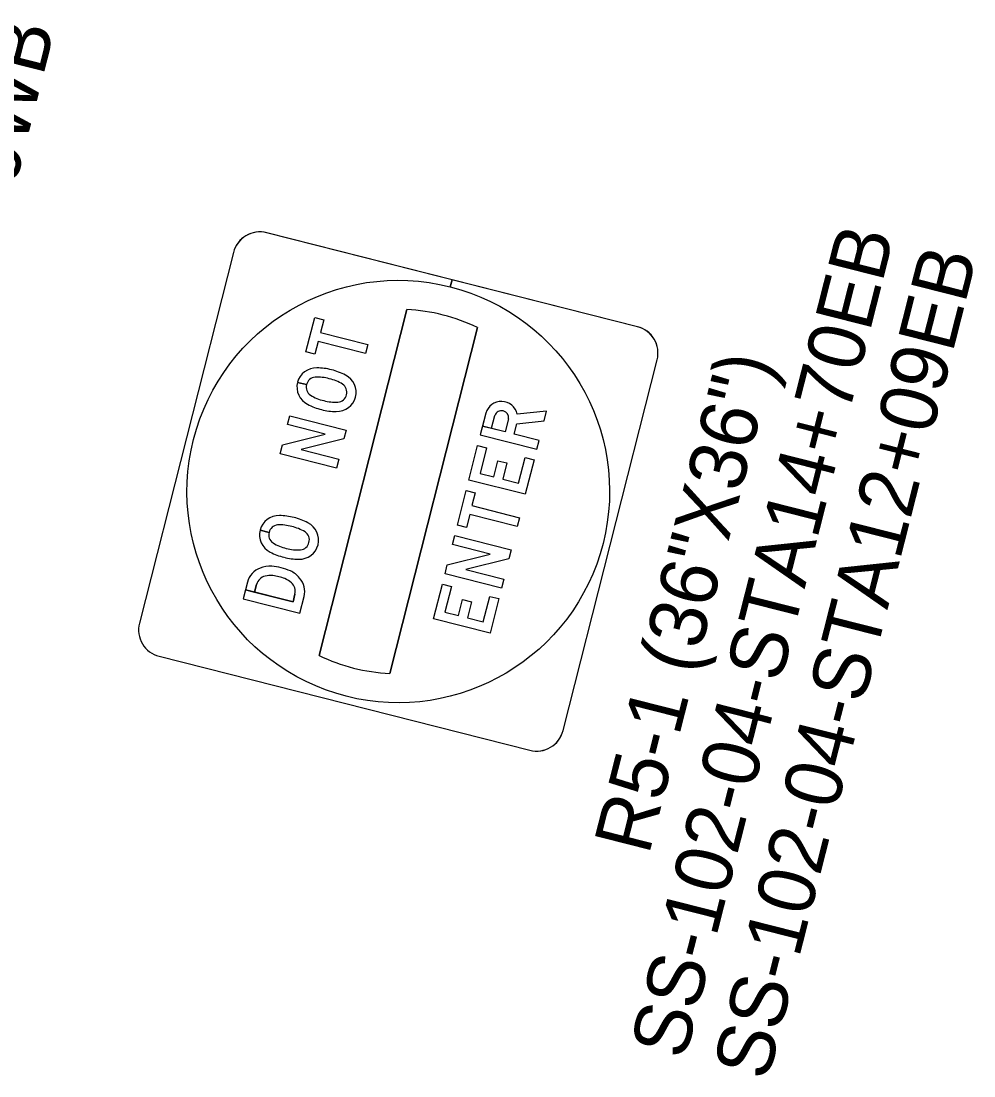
# Model space of a CAD drawing. Extents: x 670257 to 671518, y 737783 to 738188.
# Drawn here: x 670281.168 to 670285.35, y 738163.049 to 738167.682 of the extents above; entities that cross this region are included whole.
import ezdxf

# ---------------------------------------------------------------- set-up
doc = ezdxf.new("R2010")
doc.units = 0
doc.layers.add('Default', color=7, linetype='Continuous')
doc.layers.add('R_SIGN_ANNOT', color=7, linetype='Continuous')

msp = doc.modelspace()

# ---------------------------------------------------------------- linework, layer by layer
at = {"layer": 'Default'}
for p, q in [((670283.8729, 738166.3396), (670282.2455, 738166.7524)), ((670283.8729, 738166.3396), (670282.2455, 738166.7524)), ((670283.8729, 738166.3396), (670282.2456, 738166.7523)), ((670283.0593, 738166.5459), (670282.2456, 738166.7523)), ((670283.0593, 738166.5459), (670282.2456, 738166.7523)), ((670282.0998, 738166.6656), (670281.6869, 738165.0377)), ((670282.0998, 738166.6656), (670281.6869, 738165.0377)), ((670282.0999, 738166.6655), (670281.687, 738165.0376)), ((670282.0999, 738166.6655), (670281.687, 738165.0376)), ((670282.0999, 738166.6655), (670281.687, 738165.0376)), ((670283.0593, 738166.5459), (670283.0514, 738166.5149)), ((670283.8729, 738166.3396), (670283.0593, 738166.546)), ((670283.8729, 738166.3396), (670283.0593, 738166.546)), ((670282.861, 738166.4145), (670282.4757, 738164.8955)), ((670282.7857, 738164.8169), (670283.1709, 738166.3359)), ((670283.5468, 738164.566), (670283.9596, 738166.1939)), ((670283.5468, 738164.566), (670283.9596, 738166.1939)), ((670283.5468, 738164.566), (670283.9596, 738166.1939)), ((670283.5468, 738164.566), (670283.9596, 738166.1939)), ((670283.5468, 738164.566), (670283.9596, 738166.1938)), ((670282.4208, 738166.0851), (670282.3809, 738166.0952)), ((670282.3809, 738166.0952), (670282.4208, 738166.0851)), ((670282.4208, 738166.0851), (670282.3809, 738166.0952)), ((670282.3809, 738166.0952), (670282.4208, 738166.0851)), ((670282.4208, 738166.0851), (670282.4208, 738166.0851)), ((670282.4208, 738166.0851), (670282.4208, 738166.0851)), ((670283.3073, 738165.9343), (670283.293, 738165.8779)), ((670282.2562, 738165.4363), (670282.2163, 738165.4464)), ((670282.2163, 738165.4464), (670282.2562, 738165.4363)), ((670282.2562, 738165.4363), (670282.2163, 738165.4464)), ((670282.2163, 738165.4464), (670282.2562, 738165.4363)), ((670282.2562, 738165.4363), (670282.2562, 738165.4363)), ((670282.2562, 738165.4363), (670282.2562, 738165.4363)), ((670282.2012, 738165.2076), (670282.1927, 738165.1741)), ((670282.3698, 738165.1648), (670282.3613, 738165.1314)), ((670282.3698, 738165.1648), (670282.3613, 738165.1314)), ((670282.391, 738165.0819), (670282.4095, 738165.1548)), ((670281.7737, 738164.8919), (670283.401, 738164.4792)), ((670281.7737, 738164.8919), (670283.401, 738164.4792)), ((670281.7737, 738164.8919), (670283.401, 738164.4792)), ((670281.7737, 738164.8919), (670283.401, 738164.4792)), ((670281.7737, 738164.8919), (670283.401, 738164.4792))]:
    msp.add_line(p, q, dxfattribs=at)
for points in [[(670283.0593, 738166.546), (670283.0514, 738166.5149)], [(670283.0514, 738166.5149), (670283.0593, 738166.5459)], [(670283.0514, 738166.5149), (670283.0592, 738166.5459)], [(670282.4757, 738164.8955), (670282.4757, 738164.8956), (670282.861, 738166.4145), (670282.861, 738166.4146)], [(670283.1709, 738166.336), (670283.1709, 738166.3359), (670282.7856, 738164.817), (670282.7856, 738164.8169)], [(670283.2074, 738165.9596), (670283.1832, 738165.8642), (670283.4312, 738165.8013), (670283.4411, 738165.8404), (670283.3327, 738165.8679), (670283.3442, 738165.9134)], [(670283.3073, 738165.9343), (670283.293, 738165.8779), (670283.1931, 738165.9033), (670283.1832, 738165.8642), (670283.4312, 738165.8013)], [(670283.3073, 738165.9343), (670283.293, 738165.8779), (670283.1931, 738165.9033), (670283.1832, 738165.8642), (670283.4312, 738165.8013)], [(670283.2074, 738165.9596), (670283.1931, 738165.9033), (670283.2328, 738165.8933), (670283.2471, 738165.9496)], [(670283.2074, 738165.9596), (670283.1931, 738165.9033), (670283.2328, 738165.8933), (670283.2471, 738165.9496)], [(670283.293, 738165.8779), (670283.2328, 738165.8932), (670283.2471, 738165.9496)], [(670283.4312, 738165.8013), (670283.4411, 738165.8404), (670283.3327, 738165.8679), (670283.3442, 738165.9134), (670283.463, 738165.9268), (670283.4736, 738165.9687), (670283.3456, 738165.9559)], [(670283.4312, 738165.8013), (670283.4411, 738165.8404), (670283.3327, 738165.8679), (670283.3442, 738165.9134), (670283.463, 738165.9268), (670283.4736, 738165.9687), (670283.3456, 738165.9559)], [(670283.3442, 738165.9134), (670283.463, 738165.9268), (670283.4736, 738165.9687), (670283.3456, 738165.9559)], [(670282.1615, 738165.2177), (670282.143, 738165.1447), (670282.391, 738165.0819)], [(670282.1615, 738165.2177), (670282.153, 738165.1842), (670282.1927, 738165.1741), (670282.2012, 738165.2076)], [(670282.1615, 738165.2177), (670282.153, 738165.1842), (670282.1927, 738165.1741), (670282.2012, 738165.2076)], [(670282.3613, 738165.1314), (670282.153, 738165.1842), (670282.143, 738165.1447), (670282.391, 738165.0819), (670282.4095, 738165.1548)], [(670282.3613, 738165.1314), (670282.153, 738165.1842), (670282.143, 738165.1447), (670282.391, 738165.0819), (670282.4095, 738165.1548)], [(670282.1927, 738165.1741), (670282.3613, 738165.1314), (670282.3698, 738165.1648)]]:
    msp.add_lwpolyline(points, dxfattribs=at)
for points in [[(670282.4563, 738166.38), (670282.496, 738166.3699), (670282.4817, 738166.3137), (670282.6901, 738166.2609), (670282.6801, 738166.2218), (670282.4718, 738166.2746), (670282.4576, 738166.2184), (670282.4179, 738166.2285)], [(670282.4563, 738166.38), (670282.496, 738166.3699), (670282.4817, 738166.3137), (670282.6901, 738166.2609), (670282.6801, 738166.2218), (670282.4718, 738166.2746), (670282.4576, 738166.2184), (670282.4179, 738166.2285)], [(670282.4563, 738166.38), (670282.496, 738166.3699), (670282.4817, 738166.3137), (670282.6901, 738166.2609), (670282.6801, 738166.2218), (670282.4718, 738166.2746), (670282.4576, 738166.2184), (670282.4179, 738166.2285)], [(670282.5525, 738165.7184), (670282.3045, 738165.7813), (670282.3145, 738165.8209), (670282.5021, 738165.8678), (670282.337, 738165.9096), (670282.3469, 738165.9487), (670282.5949, 738165.8858), (670282.585, 738165.8467), (670282.3964, 738165.7996), (670282.5624, 738165.7575)], [(670282.5525, 738165.7184), (670282.3045, 738165.7813), (670282.3145, 738165.8209), (670282.5021, 738165.8678), (670282.337, 738165.9096), (670282.3469, 738165.9487), (670282.5949, 738165.8858), (670282.585, 738165.8467), (670282.3964, 738165.7996), (670282.5624, 738165.7575)], [(670282.5525, 738165.7184), (670282.3045, 738165.7813), (670282.3145, 738165.8209), (670282.5021, 738165.8678), (670282.337, 738165.9096), (670282.3469, 738165.9487), (670282.5949, 738165.8858), (670282.585, 738165.8467), (670282.3964, 738165.7996), (670282.5624, 738165.7575)], [(670283.2111, 738165.8077), (670283.1826, 738165.6953), (670283.2421, 738165.6802), (670283.2601, 738165.7512), (670283.2998, 738165.7412), (670283.2818, 738165.6701), (670283.3512, 738165.6525), (670283.3797, 738165.7649), (670283.4194, 738165.7549), (670283.381, 738165.6034), (670283.133, 738165.6662), (670283.1714, 738165.8177)], [(670283.2111, 738165.8077), (670283.1826, 738165.6953), (670283.2421, 738165.6802), (670283.2601, 738165.7512), (670283.2998, 738165.7412), (670283.2818, 738165.6701), (670283.3512, 738165.6525), (670283.3797, 738165.7649), (670283.4194, 738165.7549), (670283.381, 738165.6034), (670283.133, 738165.6662), (670283.1714, 738165.8177)], [(670283.2111, 738165.8077), (670283.1826, 738165.6953), (670283.2421, 738165.6802), (670283.2601, 738165.7512), (670283.2998, 738165.7412), (670283.2818, 738165.6701), (670283.3512, 738165.6525), (670283.3797, 738165.7649), (670283.4194, 738165.7549), (670283.381, 738165.6034), (670283.133, 738165.6662), (670283.1714, 738165.8177)], [(670283.1212, 738165.6199), (670283.1609, 738165.6098), (670283.1467, 738165.5536), (670283.355, 738165.5008), (670283.345, 738165.4616), (670283.1367, 738165.5145), (670283.1225, 738165.4583), (670283.0828, 738165.4684)], [(670283.1212, 738165.6199), (670283.1609, 738165.6098), (670283.1467, 738165.5536), (670283.355, 738165.5008), (670283.345, 738165.4616), (670283.1367, 738165.5145), (670283.1225, 738165.4583), (670283.0828, 738165.4684)], [(670283.1212, 738165.6199), (670283.1609, 738165.6098), (670283.1467, 738165.5536), (670283.355, 738165.5008), (670283.345, 738165.4616), (670283.1367, 738165.5145), (670283.1225, 738165.4583), (670283.0828, 738165.4684)], [(670283.2766, 738165.1916), (670283.0286, 738165.2545), (670283.0386, 738165.2941), (670283.2262, 738165.3409), (670283.0611, 738165.3828), (670283.071, 738165.4219), (670283.319, 738165.359), (670283.3091, 738165.3199), (670283.1205, 738165.2728), (670283.2865, 738165.2307)], [(670283.2766, 738165.1916), (670283.0286, 738165.2545), (670283.0386, 738165.2941), (670283.2262, 738165.3409), (670283.0611, 738165.3828), (670283.071, 738165.4219), (670283.319, 738165.359), (670283.3091, 738165.3199), (670283.1205, 738165.2728), (670283.2865, 738165.2307)], [(670283.2766, 738165.1916), (670283.0286, 738165.2545), (670283.0386, 738165.2941), (670283.2262, 738165.3409), (670283.0611, 738165.3828), (670283.071, 738165.4219), (670283.319, 738165.359), (670283.3091, 738165.3199), (670283.1205, 738165.2728), (670283.2865, 738165.2307)], [(670283.0565, 738165.1981), (670283.028, 738165.0856), (670283.0875, 738165.0705), (670283.1055, 738165.1416), (670283.1452, 738165.1316), (670283.1272, 738165.0605), (670283.1966, 738165.0429), (670283.2251, 738165.1553), (670283.2648, 738165.1452), (670283.2264, 738164.9937), (670282.9784, 738165.0566), (670283.0168, 738165.2081)], [(670283.0565, 738165.1981), (670283.028, 738165.0856), (670283.0875, 738165.0705), (670283.1055, 738165.1416), (670283.1452, 738165.1316), (670283.1272, 738165.0605), (670283.1966, 738165.0429), (670283.2251, 738165.1553), (670283.2648, 738165.1452), (670283.2264, 738164.9937), (670282.9784, 738165.0566), (670283.0168, 738165.2081)], [(670283.0565, 738165.1981), (670283.028, 738165.0856), (670283.0875, 738165.0705), (670283.1055, 738165.1416), (670283.1452, 738165.1316), (670283.1272, 738165.0605), (670283.1966, 738165.0429), (670283.2251, 738165.1553), (670283.2648, 738165.1452), (670283.2264, 738164.9937), (670282.9784, 738165.0566), (670283.0168, 738165.2081)]]:
    msp.add_lwpolyline(points, close=True, dxfattribs=at)
for centre, major_axis, ratio, start_param, end_param in [((670282.216, 738166.6361), (0.0295, 0.1163), 0.999667, 0, 1.570796), ((670282.216, 738166.6361), (0.0295, 0.1163), 0.999667, 0, 1.570796), ((670282.2161, 738166.636), (0.0295, 0.1163), 0.999667, 6.283185, 7.853982), ((670282.2161, 738166.636), (0.0295, 0.1163), 0.999667, 6.283185, 7.853982), ((670282.2161, 738166.636), (0.0295, 0.1163), 0.999667, 6.283185, 7.853982), ((670282.8233, 738165.6157), (0.2281, 0.8992), 0.999667, 0, 6.283158), ((670282.8233, 738165.6157), (0.2281, 0.8992), 0.999667, 0, 6.283158), ((670282.8233, 738165.6157), (0.2281, 0.8992), 0.999667, 0, 6.283158), ((670282.8233, 738165.6157), (0.1966, 0.7752), 0.999667, 0, 0.201359), ((670282.8233, 738165.6157), (0.1966, 0.7752), 0.999667, 0, 0.201359), ((670282.8233, 738165.6157), (0.1966, 0.7752), 0.999667, 6.081826, 6.283153), ((670282.8233, 738165.6157), (0.1966, 0.7752), 0.999667, 6.081826, 6.283153), ((670283.8434, 738166.2233), (0.0295, 0.1163), 0.999667, 4.712389, 6.283185), ((670283.8434, 738166.2233), (0.0295, 0.1163), 0.999667, 4.712389, 6.283185), ((670283.8434, 738166.2233), (0.0295, 0.1163), 0.999667, 4.712388, 6.283186), ((670283.8434, 738166.2233), (0.0295, 0.1163), 0.999667, 4.712388, 6.283186), ((670283.8434, 738166.2233), (0.0295, 0.1163), 0.999667, 4.712388, 6.283186), ((670282.4646, 738166.0734), (-0.0839, 0.0213), 0.985425, 4.940915, 6.276178), ((670282.4646, 738166.0734), (-0.0839, 0.0213), 0.985425, 4.940915, 6.27603), ((670282.4646, 738166.0734), (-0.0839, 0.0213), 0.985425, 4.940915, 6.27603), ((670282.4625, 738166.0759), (-0.0414, 0.0105), 0.985425, 5.062003, 6.314032), ((670282.4625, 738166.0759), (-0.0414, 0.0105), 0.985425, 5.062003, 6.313732), ((670282.4625, 738166.0759), (-0.0414, 0.0105), 0.985425, 5.062003, 6.313732), ((670282.4694, 738165.9281), (-0.1867, 0.0473), 0.985425, 4.688261, 5.016143), ((670282.4694, 738165.9281), (-0.1867, 0.0473), 0.985425, 4.688261, 5.016143), ((670282.4694, 738165.9281), (-0.1867, 0.0473), 0.985425, 4.688261, 5.016143), ((670282.4656, 738165.8998), (-0.2545, 0.0645), 0.985425, 4.707364, 4.955713), ((670282.4656, 738165.8998), (-0.2545, 0.0645), 0.985425, 4.707364, 4.955713), ((670282.4656, 738165.8998), (-0.2545, 0.0645), 0.985425, 4.707364, 4.955713), ((670282.4682, 738165.8992), (-0.2545, 0.0645), 0.985425, 4.469065, 4.717414), ((670282.4682, 738165.8992), (-0.2545, 0.0645), 0.985425, 4.469065, 4.717414), ((670282.4682, 738165.8992), (-0.2545, 0.0645), 0.985425, 4.469065, 4.717414), ((670282.5518, 738166.0513), (-0.0839, 0.0213), 0.985425, 3.1486, 4.483863), ((670282.5518, 738166.0513), (-0.0839, 0.0213), 0.985425, 3.1486, 4.483863), ((670282.5518, 738166.0513), (-0.0839, 0.0213), 0.985425, 3.1486, 4.483863), ((670282.4649, 738166.0745), (-0.0839, 0.0213), 0.985425, 0.007008, 1.34227), ((670282.4649, 738166.0745), (-0.0839, 0.0213), 0.985425, 0.007008, 1.34227), ((670282.4649, 738166.0745), (-0.0839, 0.0213), 0.985425, 0.007008, 1.34227), ((670282.4619, 738166.0733), (-0.0414, 0.0105), 0.985425, 6.252339, 7.504367), ((670282.4619, 738166.0733), (-0.0414, 0.0105), 0.985425, 6.252339, 7.504367), ((670282.4619, 738166.0733), (-0.0414, 0.0105), 0.985425, 6.252339, 7.504367), ((670282.4784, 738165.9258), (-0.1867, 0.0473), 0.985425, 4.408635, 4.736517), ((670282.4784, 738165.9258), (-0.1867, 0.0473), 0.985425, 4.408635, 4.736517), ((670282.4784, 738165.9258), (-0.1867, 0.0473), 0.985425, 4.408635, 4.736517), ((670282.5548, 738166.0525), (-0.0414, 0.0105), 0.985425, 3.110746, 4.362774), ((670282.5548, 738166.0525), (-0.0414, 0.0105), 0.985425, 3.110746, 4.362775), ((670282.5548, 738166.0525), (-0.0414, 0.0105), 0.985425, 3.110746, 4.362775), ((670282.5383, 738166.2), (-0.1867, 0.0473), 0.985425, 1.267043, 1.594924), ((670282.5383, 738166.2), (-0.1867, 0.0473), 0.985425, 1.267042, 1.594924), ((670282.5383, 738166.2), (-0.1867, 0.0473), 0.985425, 1.267042, 1.594924), ((670282.5521, 738166.0524), (-0.0839, 0.0213), 0.985425, 1.799323, 3.134585), ((670282.5521, 738166.0524), (-0.0839, 0.0213), 0.985425, 1.799323, 3.134585), ((670282.5521, 738166.0524), (-0.0839, 0.0213), 0.985425, 1.799323, 3.134585), ((670282.5542, 738166.0499), (-0.0414, 0.0105), 0.985425, 1.920411, 3.172439), ((670282.5542, 738166.0499), (-0.0414, 0.0105), 0.985425, 1.920411, 3.172439), ((670282.5542, 738166.0499), (-0.0414, 0.0105), 0.985425, 1.920411, 3.172439), ((670282.5485, 738166.2266), (-0.2545, 0.0645), 0.985425, 1.327472, 1.575821), ((670282.5485, 738166.2266), (-0.2545, 0.0645), 0.985425, 1.327472, 1.575821), ((670282.5485, 738166.2266), (-0.2545, 0.0645), 0.985425, 1.327472, 1.575821), ((670282.5473, 738166.1977), (-0.1867, 0.0473), 0.985425, 1.546668, 1.87455), ((670282.5473, 738166.1977), (-0.1867, 0.0473), 0.985425, 1.546668, 1.87455), ((670282.5473, 738166.1977), (-0.1867, 0.0473), 0.985425, 1.546668, 1.87455), ((670283.2762, 738165.9409), (-0.0691, 0.0175), 0.985328, 3.608399, 6.264838), ((670283.2762, 738165.9409), (-0.0691, 0.0175), 0.985328, 3.608399, 6.264838), ((670283.2762, 738165.9409), (-0.0691, 0.0175), 0.985328, 3.608399, 6.264838), ((670282.5511, 738166.226), (-0.2545, 0.0645), 0.985425, 1.565772, 1.814121), ((670282.5511, 738166.226), (-0.2545, 0.0645), 0.985425, 1.565772, 1.814121), ((670282.5511, 738166.226), (-0.2545, 0.0645), 0.985425, 1.565772, 1.814121), ((670283.2767, 738165.9399), (-0.0302, 0.0077), 0.985328, 3.211299, 6.213479), ((670283.2767, 738165.9399), (-0.0302, 0.0077), 0.985328, 3.211299, 6.213479), ((670283.2767, 738165.9399), (-0.0302, 0.0077), 0.985328, 3.211299, 6.213479), ((670282.3001, 738165.4246), (-0.0839, 0.0213), 0.985425, 4.940915, 6.276178), ((670282.3001, 738165.4246), (-0.0839, 0.0213), 0.985425, 4.940915, 6.27603), ((670282.3001, 738165.4246), (-0.0839, 0.0213), 0.985425, 4.940915, 6.27603), ((670282.298, 738165.4271), (-0.0414, 0.0105), 0.985425, 5.062003, 6.314032), ((670282.298, 738165.4271), (-0.0414, 0.0105), 0.985425, 5.062003, 6.313732), ((670282.298, 738165.4271), (-0.0414, 0.0105), 0.985425, 5.062003, 6.313732), ((670282.3048, 738165.2793), (-0.1867, 0.0473), 0.985425, 4.688261, 5.016143), ((670282.3048, 738165.2793), (-0.1867, 0.0473), 0.985425, 4.688261, 5.016143), ((670282.3048, 738165.2793), (-0.1867, 0.0473), 0.985425, 4.688261, 5.016143), ((670282.3011, 738165.251), (-0.2545, 0.0645), 0.985425, 4.707364, 4.955713), ((670282.3011, 738165.251), (-0.2545, 0.0645), 0.985425, 4.707364, 4.955713), ((670282.3011, 738165.251), (-0.2545, 0.0645), 0.985425, 4.707364, 4.955713), ((670282.3036, 738165.2504), (-0.2545, 0.0645), 0.985425, 4.469065, 4.717414), ((670282.3036, 738165.2504), (-0.2545, 0.0645), 0.985425, 4.469065, 4.717414), ((670282.3036, 738165.2504), (-0.2545, 0.0645), 0.985425, 4.469065, 4.717414), ((670282.3872, 738165.4025), (-0.0839, 0.0213), 0.985425, 3.1486, 4.483863), ((670282.3872, 738165.4025), (-0.0839, 0.0213), 0.985425, 3.1486, 4.483863), ((670282.3872, 738165.4025), (-0.0839, 0.0213), 0.985425, 3.1486, 4.483863), ((670282.3004, 738165.4257), (-0.0839, 0.0213), 0.985425, 0.007008, 1.34227), ((670282.3004, 738165.4257), (-0.0839, 0.0213), 0.985425, 0.007008, 1.34227), ((670282.3004, 738165.4257), (-0.0839, 0.0213), 0.985425, 0.007008, 1.34227), ((670282.2973, 738165.4245), (-0.0414, 0.0105), 0.985425, 6.252339, 7.504367), ((670282.2973, 738165.4245), (-0.0414, 0.0105), 0.985425, 6.252339, 7.504367), ((670282.2973, 738165.4245), (-0.0414, 0.0105), 0.985425, 6.252339, 7.504367), ((670282.3138, 738165.277), (-0.1867, 0.0473), 0.985425, 4.408635, 4.736517), ((670282.3138, 738165.277), (-0.1867, 0.0473), 0.985425, 4.408635, 4.736517), ((670282.3138, 738165.277), (-0.1867, 0.0473), 0.985425, 4.408635, 4.736517), ((670282.3903, 738165.4037), (-0.0414, 0.0105), 0.985425, 3.110746, 4.362774), ((670282.3903, 738165.4037), (-0.0414, 0.0105), 0.985425, 3.110746, 4.362775), ((670282.3903, 738165.4037), (-0.0414, 0.0105), 0.985425, 3.110746, 4.362775), ((670282.3738, 738165.5512), (-0.1867, 0.0473), 0.985425, 1.267043, 1.594924), ((670282.3738, 738165.5512), (-0.1867, 0.0473), 0.985425, 1.267042, 1.594924), ((670282.3738, 738165.5512), (-0.1867, 0.0473), 0.985425, 1.267042, 1.594924), ((670282.3875, 738165.4036), (-0.0839, 0.0213), 0.985425, 1.799323, 3.134585), ((670282.3875, 738165.4036), (-0.0839, 0.0213), 0.985425, 1.799323, 3.134585), ((670282.3875, 738165.4036), (-0.0839, 0.0213), 0.985425, 1.799323, 3.134585), ((670282.3896, 738165.4011), (-0.0414, 0.0105), 0.985425, 1.920411, 3.172439), ((670282.3896, 738165.4011), (-0.0414, 0.0105), 0.985425, 1.920411, 3.172439), ((670282.3896, 738165.4011), (-0.0414, 0.0105), 0.985425, 1.920411, 3.172439), ((670282.3839, 738165.5778), (-0.2545, 0.0645), 0.985425, 1.327472, 1.575821), ((670282.3839, 738165.5778), (-0.2545, 0.0645), 0.985425, 1.327472, 1.575821), ((670282.3839, 738165.5778), (-0.2545, 0.0645), 0.985425, 1.327472, 1.575821), ((670282.3828, 738165.5489), (-0.1867, 0.0473), 0.985425, 1.546668, 1.87455), ((670282.3828, 738165.5489), (-0.1867, 0.0473), 0.985425, 1.546668, 1.87455), ((670282.3828, 738165.5489), (-0.1867, 0.0473), 0.985425, 1.546668, 1.87455), ((670282.2603, 738165.1759), (-0.1093, 0.0277), 0.994387, 4.893794, 5.353227), ((670282.2603, 738165.1759), (-0.1093, 0.0277), 0.994387, 4.893794, 5.353227), ((670282.2603, 738165.1759), (-0.1093, 0.0277), 0.994387, 4.893794, 5.353227), ((670282.2411, 738165.0031), (-0.2787, 0.0707), 0.994387, 4.719381, 4.866939), ((670282.2411, 738165.0031), (-0.2787, 0.0707), 0.994387, 4.719381, 4.866939), ((670282.2411, 738165.0031), (-0.2787, 0.0707), 0.994387, 4.719381, 4.866939), ((670282.3865, 738165.5772), (-0.2545, 0.0645), 0.985425, 1.565772, 1.814121), ((670282.3865, 738165.5772), (-0.2545, 0.0645), 0.985425, 1.565772, 1.814121), ((670282.3865, 738165.5772), (-0.2545, 0.0645), 0.985425, 1.565772, 1.814121), ((670282.2472, 738165.1971), (-0.0854, 0.0217), 0.994387, 5.308841, 6.296324), ((670282.2472, 738165.1971), (-0.0854, 0.0217), 0.994387, 5.308841, 6.296324), ((670282.2472, 738165.1971), (-0.0854, 0.0217), 0.994387, 5.308841, 6.296324), ((670282.2518, 738165.1938), (-0.0508, 0.0129), 0.994387, 5.209958, 6.265172), ((670282.2518, 738165.1938), (-0.0508, 0.0129), 0.994387, 5.209958, 6.265172), ((670282.2518, 738165.1938), (-0.0508, 0.0129), 0.994387, 5.209958, 6.265172), ((670282.2612, 738165.1598), (-0.0851, 0.0216), 0.994387, 4.827156, 5.217241), ((670282.2612, 738165.1598), (-0.0851, 0.0216), 0.994387, 4.827156, 5.217241), ((670282.2612, 738165.1598), (-0.0851, 0.0216), 0.994387, 4.827156, 5.217241), ((670282.2477, 738165.0561), (-0.1871, 0.0475), 0.994387, 4.688208, 4.829332), ((670282.2477, 738165.0561), (-0.1871, 0.0475), 0.994387, 4.688208, 4.829332), ((670282.2477, 738165.0561), (-0.1871, 0.0475), 0.994387, 4.688208, 4.829332), ((670282.2567, 738165.0538), (-0.1871, 0.0475), 0.994387, 4.595446, 4.73657), ((670282.2567, 738165.0538), (-0.1871, 0.0475), 0.994387, 4.595446, 4.73657), ((670282.2567, 738165.0538), (-0.1871, 0.0475), 0.994387, 4.595446, 4.73657), ((670282.2372, 738165.0041), (-0.2787, 0.0707), 0.994387, 4.557839, 4.705397), ((670282.2372, 738165.0041), (-0.2787, 0.0707), 0.994387, 4.557839, 4.705397), ((670282.2372, 738165.0041), (-0.2787, 0.0707), 0.994387, 4.557839, 4.705397), ((670282.3028, 738165.1651), (-0.1093, 0.0277), 0.994387, 4.071551, 4.530984), ((670282.3028, 738165.1651), (-0.1093, 0.0277), 0.994387, 4.071551, 4.530984), ((670282.3028, 738165.1651), (-0.1093, 0.0277), 0.994387, 4.071551, 4.530984), ((670282.2944, 738165.1514), (-0.0851, 0.0216), 0.994387, 4.207537, 4.597622), ((670282.2944, 738165.1514), (-0.0851, 0.0216), 0.994387, 4.207537, 4.597622), ((670282.2944, 738165.1514), (-0.0851, 0.0216), 0.994387, 4.207537, 4.597622), ((670282.3188, 738165.1768), (-0.0508, 0.0129), 0.994387, 3.159606, 4.21482), ((670282.3188, 738165.1768), (-0.0508, 0.0129), 0.994387, 3.159606, 4.21482), ((670282.3188, 738165.1768), (-0.0508, 0.0129), 0.994387, 3.159606, 4.21482), ((670282.3244, 738165.1776), (-0.0854, 0.0217), 0.994387, 3.128454, 4.115937), ((670282.3244, 738165.1776), (-0.0854, 0.0217), 0.994387, 3.128454, 4.115937), ((670282.3244, 738165.1776), (-0.0854, 0.0217), 0.994387, 3.128454, 4.115937), ((670281.8032, 738165.0082), (0.0295, 0.1163), 0.999667, 1.570796, 3.141593), ((670281.8032, 738165.0082), (0.0295, 0.1163), 0.999667, 1.570796, 3.141593), ((670281.8032, 738165.0082), (0.0295, 0.1163), 0.999667, 1.570796, 3.141593), ((670281.8032, 738165.0082), (0.0295, 0.1163), 0.999667, 1.570796, 3.141593), ((670281.8032, 738165.0082), (0.0295, 0.1163), 0.999667, 1.570796, 3.141593), ((670282.8233, 738165.6157), (0.1966, 0.7752), 0.999667, 2.940234, 3.342952), ((670282.8233, 738165.6157), (0.1966, 0.7752), 0.999667, 2.940234, 3.342952), ((670283.4305, 738164.5954), (0.0295, 0.1163), 0.999667, 3.141593, 4.712389), ((670283.4305, 738164.5954), (0.0295, 0.1163), 0.999667, 3.141593, 4.712389), ((670283.4305, 738164.5954), (0.0295, 0.1163), 0.999667, 3.141592, 4.71239), ((670283.4305, 738164.5954), (0.0295, 0.1163), 0.999667, 3.141593, 4.712389), ((670283.4305, 738164.5954), (0.0295, 0.1163), 0.999667, 3.141593, 4.712389)]:
    msp.add_ellipse(centre, major_axis=major_axis, ratio=ratio, start_param=start_param, end_param=end_param, dxfattribs=at)

# ---------------------------------------------------------------- texts
msp.add_text('SS-072-04-STA206+60WB', height=0.25, rotation=75.7686, dxfattribs=at).set_placement((670280.3289, 738163.7507))
at = {"layer": 'R_SIGN_ANNOT'}
for s, p in [('SS-102-04-STA14+70EB', (670284.0814, 738163.1146)), ('SS-102-04-STA12+09EB', (670284.4449, 738163.0224)), ('R5-1 (36"X36")', (670283.9228, 738164.0148))]:
    msp.add_text(s, height=0.25, rotation=75.7686, dxfattribs=at).set_placement(p)

doc.saveas('drawing.dxf')
